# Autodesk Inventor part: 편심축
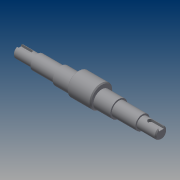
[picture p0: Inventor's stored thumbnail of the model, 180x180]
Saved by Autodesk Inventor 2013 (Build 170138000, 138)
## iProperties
Created: 2014-12
Part Number: 편심축
Material: Generic
Document SubType Name: Modeling
Designer: HS002
Density: 1 g/cm^3
Author: HS002
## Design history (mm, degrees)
sketch "스케치1"
  geometry: L1 (-75.5, 0)-(75.5, 0); L2 (-75.5, 0)-(-75.5, 6); L3 (-75.5, 6)-(-55.5, 6); L4 (-55.5, 6)-(-55.5, 7.5); L5 (-55.5, 7.5)-(-30.5, 7.5); L6 (-30.5, 7.5)-(-30.5, 9); L7 (-30.5, 9)-(-12.5, 9); L8 (12.5, 9)-(30.5, 9); L9 (30.5, 9)-(30.5, 7.5); L10 (30.5, 7.5)-(55.5, 7.5); L11 (55.5, 7.5)-(55.5, 6); L12 (55.5, 6)-(75.5, 6); L13 (75.5, 6)-(75.5, 0); L14 (12.5, 9)-(-12.5, 9); 2 further points
  constraints: 28 end point, 7 parallel, 4 perpendicular, 1 coincident, 1 collinear, 1 horizontal, 1 midpoint
  dimensions: "d0" = 151 distance of L1.start L1.end; "d2" = 12 diameter of L3 L1; "d3" = 12 diameter of L12 L1; "d4" = 15 diameter of L10 L1; "d5" = 18 diameter of L8 L1; "d7" = 18 diameter of L7 L1; "d8" = 15 diameter of L5 L1; "d9" = 20 distance of L2.end L3.end; "d10" = 25 distance of L4.end L5.end; "d13" = 25 distance of L9.end L10.end; "d14" = 20 distance of L11.end L12.end
revolve "회전1" sketch "스케치1" stored, may be unused: angle "d15" = 90 deg
node "작업 평면1"
sketch "스케치2"
  geometry: L1 (-75.5, -6)-(-75.5, 6) reference; L2 (-61.5, 0)-(-75.5, 0); L3 (-64, -2.5)-(-75.5, -2.5); L4 (-64, 2.5)-(-75.5, 2.5); L5 (-75.5, 2.5)-(-75.5, -2.5); L6 (75.5, 0)-(61.5, 0); L7 (64, 2.5)-(75.5, 2.5); L8 (64, -2.5)-(75.5, -2.5); L9 (75.5, -2.5)-(75.5, 2.5); A1 r 2.5 centre (-64, 0) between (-64, -2.5) and (-64, 2.5); A2 r 2.5 centre (64, 0) between (64, 2.5) and (64, -2.5); 1 further point
  constraints: 16 end point, 6 point on circle, 4 tangent, 3 perpendicular, 2 centre point, 2 parallel, 2 point on line, 1 midpoint
  dimensions: "d17" = 5 diameter of A1; "d19" = 14 distance of L2.start L2.end; "d22" = 5 diameter of A2; "d23" = 14 distance of L6.start L6.end
extrude "돌출2" cut sketch "스케치2" distance "d24" = 3; taper "d25" = 0 deg
chamfer "모따기1" distance "d26" = 1; stored, may be unused: second distance "d27" = 2, angle "d28" = 45 deg
sketch "스케치3"
  geometry: L1 (12.5, 2)-(-12.5, 2); L2 (30.5, 7.5)-(30.5, -7.5) reference; L3 (-30.5, 7.5)-(-30.5, -7.5) reference; L4 (12.5, 14)-(-12.5, 14); L5 (-12.5, 14)-(-12.5, 2); L6 (12.5, 2)-(12.5, 14); 1 further point
  constraints: 8 end point, 2 perpendicular, 1 horizontal, 1 parallel
  dimensions: "d29" = 2 distance from line of point (0, 0) L1; "d30" = 18 distance from line of L1.start L2; "d31" = 18 distance from line of L1.end L3; "d32" = 24 diameter of L4 L1
revolve "회전2" sketch "스케치3" stored, may be unused: angle "d33" = 90 deg
chamfer "모따기2" distance "d34" = 1; stored, may be unused: second distance "d35" = 2, angle "d36" = 45 deg
node "솔리드1"
other parameters: "d16" = 6
